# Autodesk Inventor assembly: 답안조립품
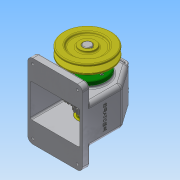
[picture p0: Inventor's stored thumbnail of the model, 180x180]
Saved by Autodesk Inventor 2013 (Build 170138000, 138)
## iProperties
Created: 2016-12
Part Number: 답안조립품
Document SubType Name: Assembly
Designer: Administrator
Author: Administrator
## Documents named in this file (15)
- C:\Users\Administrator\Desktop\461208V1016\답안조립품.iam
- C:\Users\Administrator\Desktop\461208V1016\본체.ipt
- C:\Users\Administrator\Desktop\461208V1016\V-벨트풀리.ipt
- C:\Users\Administrator\Desktop\461208V1016\뒤커버.ipt
- C:\Users\Administrator\Desktop\461208V1016\멈춤나사 - M4x10.ipt
- C:\Users\Administrator\Desktop\461208V1016\베어링 6203.ipt
- C:\Users\Administrator\Desktop\461208V1016\볼트 M3 x 8.ipt
- C:\Users\Administrator\Desktop\461208V1016\볼트 M3 x 10.ipt
- C:\Users\Administrator\Desktop\461208V1016\부시.ipt
- C:\Users\Administrator\Desktop\461208V1016\스퍼기어.ipt
- C:\Users\Administrator\Desktop\461208V1016\앞커버.ipt
- C:\Users\Administrator\Desktop\461208V1016\오일씰 28 40 8.ipt
- C:\Users\Administrator\Desktop\461208V1016\축.ipt
- C:\Users\Administrator\Desktop\461208V1016\키 - 5 x 5 x 18.ipt
- C:\Users\Administrator\Desktop\461208V1016\키 - 6 x 6 x 22.ipt
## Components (9 placed, 3 different names)
1. V-벨트풀리:1 — 각도:1
2. ISO 4762 M3 x 8:1
3. ISO 4762 M3 x 8:2
4. ISO 4762 M3 x 8:3
5. ISO 4762 M3 x 8:4
6. ISO 4762 M3 x 10:1
7. ISO 4762 M3 x 10:2
8. ISO 4762 M3 x 10:3
9. ISO 4762 M3 x 10:4
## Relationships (1: Angle 1)
- 각도:1 [Angle]: V-벨트풀리:1
